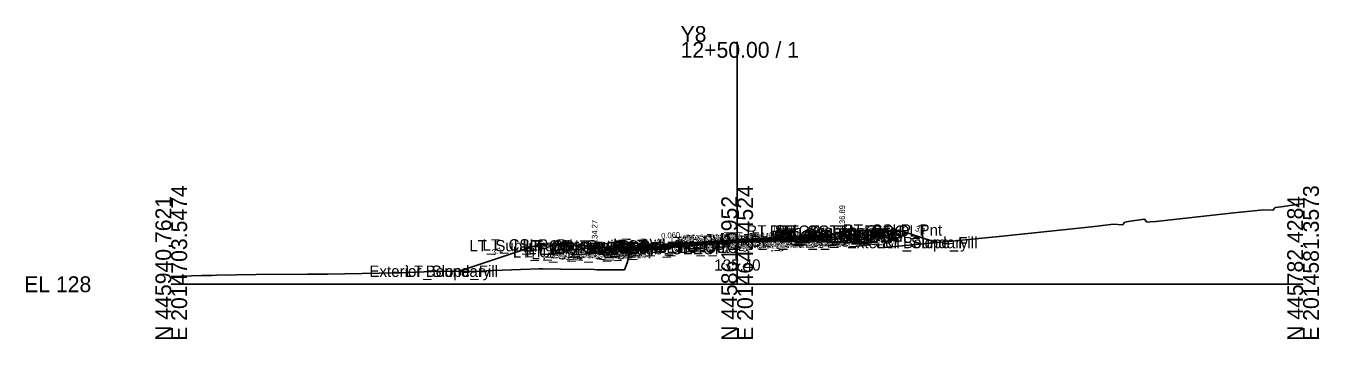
# Model space of a CAD drawing. Extents: x -26 to 1403, y -10 to 8043.
# Drawn here: x -25.7 to 202.8, y 4990.3 to 5045.6 of the extents above; entities that cross this region are included whole.
import ezdxf

# ---------------------------------------------------------------- set-up
doc = ezdxf.new("R2010")
doc.units = 0
for name, color, linetype in [('Default', 7, 'Continuous'), ('Exist CMT Pavement', 7, 'Continuous'), ('Exist Cross Section Cell', 7, 'Continuous'), ('Exist XS Center Line Elevation Label', 7, 'Continuous'), ('Exist XS Ground Line', 7, 'Continuous'), ('Prop CMT Conc Surface', 7, 'Continuous'), ('Prop CMT Concrete Structures', 7, 'Continuous'), ('Prop CMT Pvmt Course 1', 7, 'Continuous'), ('Prop CMT Pvmt Course 1 CG', 7, 'Continuous'), ('Prop CMT Pvmt Course 1 Wedge', 7, 'Continuous'), ('Prop CMT Pvmt Course 2', 7, 'Continuous'), ('Prop CMT Pvmt Course 2 Wedge', 7, 'Continuous'), ('Prop CMT Pvmt Course 3', 7, 'Continuous'), ('Prop CMT Pvmt Course 3 Wedge', 7, 'Continuous'), ('Prop CMT Pvmt Surface', 7, 'Continuous'), ('Prop CMT Pvmt Wedge Surface 1', 7, 'Continuous'), ('Prop CMT Pvmt Wedge Surface 2', 7, 'Continuous'), ('Prop CMT Pvmt Wedge Surface 3', 7, 'Continuous'), ('Prop CMT Slope Grass', 7, 'Continuous'), ('Prop CMT Subgrade Earthwork', 7, 'Continuous'), ('Prop XS Earthwork Shape', 7, 'Continuous'), ('Prop XS Hydro Elevations', 7, 'Continuous'), ('Prop XS SE Text', 7, 'Continuous'), ('Prop XS Side Slope Text', 7, 'Continuous'), ('Prop XS Wedging', 7, 'Continuous'), ('Scratch_Level_0', 7, 'Continuous')]:
    doc.layers.add(name, color=color, linetype=linetype)

msp = doc.modelspace()

# ---------------------------------------------------------------- linework, layer by layer
at = {"layer": 'Exist CMT Pavement'}
msp.add_lwpolyline([(88.23, 5006.52), (90.89, 5006.74), (99.12, 5007.37), (100, 5007.4), (105.99, 5007.58), (107.65, 5007.65), (107.65, 5007.65)], dxfattribs=at)
at = {"layer": 'Exist Cross Section Cell'}
for p, q in [((100, 5000), (100, 5042.8)), ((0, 5000), (100, 5000)), ((100, 5000), (200, 5000))]:
    msp.add_line(p, q, dxfattribs=at)
at = {"layer": 'Exist XS Ground Line'}
msp.add_lwpolyline([(0, 5001.36), (5.4, 5001.53), (7.09, 5001.55), (8.04, 5001.58), (15.03, 5001.75), (24.09, 5001.78), (27.66, 5001.81), (39.75, 5002), (40.46, 5002.01), (47.5, 5002.33), (52.93, 5002.28), (54.63, 5002.33), (56.83, 5002.4), (65.03, 5002.72), (65.65, 5002.7), (68.86, 5002.65), (74.71, 5002.59), (75.24, 5002.56), (78.78, 5002.55), (80.09, 5002.56), (80.59, 5003.81), (81.22, 5006.05), (86.99, 5006.42), (88.23, 5006.52), (90.89, 5006.74), (99.12, 5007.37), (100, 5007.4), (105.99, 5007.58), (107.65, 5007.65), (109.17, 5007.71), (110.08, 5007.71), (111.02, 5007.97), (112.19, 5007.9), (114.59, 5007.88), (116.98, 5007.6), (117.9, 5007.54), (120.35, 5007.32), (122.79, 5007.18), (124.31, 5007.03), (124.61, 5006.96), (125.03, 5006.46), (126.61, 5006.56), (138.59, 5007.68), (140.8, 5007.9), (146.27, 5008.41), (162.62, 5010.13), (166.53, 5010.6), (168.11, 5010.49), (168.53, 5010.99), (169.53, 5011.15), (172, 5011.47), (172.42, 5010.97), (172.96, 5011.01), (174, 5011.07), (187.78, 5012.59), (193.09, 5013.17), (194.67, 5013.07), (195.09, 5013.57), (196.15, 5013.69), (200, 5014.27)], dxfattribs=at)
at = {"layer": 'Prop CMT Conc Surface'}
for points in [[(116.56, 5008.85), (118.56, 5008.89)], [(118.56, 5008.89), (118.56, 5009.39), (119.06, 5009.39)], [(74.82, 5006.27), (74.82, 5006.77), (74.32, 5006.77)], [(76.82, 5006.47), (74.82, 5006.27)]]:
    msp.add_lwpolyline(points, dxfattribs=at)
at = {"layer": 'Prop CMT Concrete Structures'}
for points in [[(116.56, 5008.85), (118.56, 5008.89), (118.56, 5009.39), (119.06, 5009.39)], [(119.06, 5009.39), (119.06, 5008.42), (116.56, 5008.27)], [(116.56, 5008.27), (116.56, 5008.85)], [(76.82, 5006.47), (74.82, 5006.27), (74.82, 5006.77), (74.32, 5006.77)], [(74.32, 5006.77), (74.32, 5005.73), (76.82, 5005.88)], [(76.82, 5005.88), (76.82, 5006.47)]]:
    msp.add_lwpolyline(points, dxfattribs=at)
at = {"layer": 'Prop CMT Pvmt Course 1'}
for points in [[(100, 5007.86), (76.82, 5006.47)], [(88.23, 5007.03), (100, 5007.73)], [(100, 5007.86), (116.56, 5008.85)], [(107.65, 5008.19), (100, 5007.73)], [(100, 5007.61), (100, 5007.86)], [(100, 5007.61), (100, 5007.86)], [(100, 5007.73), (100, 5007.61), (100, 5007.61)], [(100, 5007.73), (100, 5007.61), (100, 5007.61)], [(116.56, 5008.6), (107.65, 5008.07)], [(107.65, 5008.07), (107.65, 5008.19)], [(116.56, 5008.85), (116.56, 5008.6)], [(76.82, 5006.22), (88.23, 5006.9)], [(76.82, 5006.47), (76.82, 5006.22)], [(88.23, 5006.9), (88.23, 5007.03)]]:
    msp.add_lwpolyline(points, dxfattribs=at)
at = {"layer": 'Prop CMT Pvmt Course 1 CG'}
for points in [[(116.56, 5008.27), (119.56, 5008.45), (119.83, 5008.17)], [(116.56, 5007.97), (116.56, 5008.27)], [(119.83, 5008.17), (116.56, 5007.97)], [(76.82, 5005.88), (73.82, 5005.7), (73.51, 5005.39)], [(73.51, 5005.39), (76.82, 5005.59)], [(76.82, 5005.59), (76.82, 5005.88)]]:
    msp.add_lwpolyline(points, dxfattribs=at)
at = {"layer": 'Prop CMT Pvmt Course 1 Wedge'}
for points in [[(100, 5007.73), (88.23, 5007.03)], [(100, 5007.73), (107.65, 5008.19)]]:
    msp.add_lwpolyline(points, dxfattribs=at)
at = {"layer": 'Prop CMT Pvmt Course 2'}
for points in [[(107.65, 5008.07), (116.56, 5008.6)], [(116.56, 5008.35), (107.65, 5007.82)], [(107.65, 5007.82), (107.65, 5008.07)], [(116.56, 5008.6), (116.56, 5008.35)], [(88.23, 5006.9), (76.82, 5006.22)], [(76.82, 5005.97), (88.23, 5006.65)], [(76.82, 5006.22), (76.82, 5005.97)], [(88.23, 5006.65), (88.23, 5006.9)]]:
    msp.add_lwpolyline(points, dxfattribs=at)
at = {"layer": 'Prop CMT Pvmt Course 2 Wedge'}
for points in [[(100, 5007.61), (88.23, 5006.9)], [(100, 5007.61), (107.65, 5008.07)]]:
    msp.add_lwpolyline(points, dxfattribs=at)
at = {"layer": 'Prop CMT Pvmt Course 3'}
for points in [[(107.65, 5007.82), (116.56, 5008.35)], [(116.56, 5007.97), (107.65, 5007.44)], [(107.65, 5007.44), (107.65, 5007.82)], [(116.56, 5008.35), (116.56, 5007.97)], [(88.23, 5006.65), (76.82, 5005.97)], [(76.82, 5005.59), (88.23, 5006.28)], [(76.82, 5005.97), (76.82, 5005.59)], [(88.23, 5006.28), (88.23, 5006.65)]]:
    msp.add_lwpolyline(points, dxfattribs=at)
at = {"layer": 'Prop CMT Pvmt Course 3 Wedge'}
for points in [[(100, 5007.36), (88.23, 5006.65)], [(100, 5007.36), (107.65, 5007.82)]]:
    msp.add_lwpolyline(points, dxfattribs=at)
at = {"layer": 'Prop CMT Pvmt Surface'}
for points in [[(100, 5007.86), (76.82, 5006.47)], [(100, 5007.86), (116.56, 5008.85)]]:
    msp.add_lwpolyline(points, dxfattribs=at)
at = {"layer": 'Prop CMT Pvmt Wedge Surface 1'}
for points in [[(100, 5007.73), (88.23, 5007.03)], [(100, 5007.73), (107.65, 5008.19)], [(107.65, 5008.07), (116.56, 5008.6)], [(107.65, 5008.19), (107.65, 5008.07)], [(116.56, 5008.6), (116.56, 5008.85)], [(88.23, 5006.9), (76.82, 5006.22)], [(76.82, 5006.22), (76.82, 5006.47)], [(88.23, 5007.03), (88.23, 5006.9)]]:
    msp.add_lwpolyline(points, dxfattribs=at)
at = {"layer": 'Prop CMT Pvmt Wedge Surface 2'}
for points in [[(100, 5007.61), (76.82, 5006.22)], [(100, 5007.61), (116.56, 5008.6)], [(116.56, 5008.6), (116.56, 5008.85)], [(76.82, 5006.22), (76.82, 5006.47)]]:
    msp.add_lwpolyline(points, dxfattribs=at)
at = {"layer": 'Prop CMT Pvmt Wedge Surface 3'}
for points in [[(100, 5007.36), (76.82, 5005.97)], [(100, 5007.36), (116.56, 5008.35)], [(116.56, 5008.35), (116.56, 5008.85)], [(76.82, 5005.97), (76.82, 5006.47)]]:
    msp.add_lwpolyline(points, dxfattribs=at)
at = {"layer": 'Prop CMT Slope Grass'}
for points in [[(119.06, 5009.39), (128.56, 5009.58), (135.21, 5007.36)], [(74.32, 5006.77), (64.82, 5006.96), (50.86, 5002.3)]]:
    msp.add_lwpolyline(points, dxfattribs=at)
at = {"layer": 'Prop CMT Subgrade Earthwork'}
for points in [[(107.65, 5007.44), (116.56, 5007.97)], [(107.65, 5007.44), (107.65, 5007.65)], [(116.56, 5007.97), (119.83, 5008.17), (121.09, 5009.43)], [(76.82, 5005.59), (73.51, 5005.39), (72.09, 5006.81)], [(88.23, 5006.28), (76.82, 5005.59)], [(88.23, 5006.28), (88.23, 5006.52)]]:
    msp.add_lwpolyline(points, dxfattribs=at)
at = {"layer": 'Prop XS Earthwork Shape'}
for points in [[(114.71, 5007.86), (116.98, 5007.6), (117.9, 5007.54), (120.35, 5007.32), (122.79, 5007.18), (124.31, 5007.03), (124.61, 5006.96), (125.03, 5006.46), (126.61, 5006.56), (135.21, 5007.36), (128.56, 5009.58), (121.09, 5009.43), (119.83, 5008.17), (116.56, 5007.97)], [(114.71, 5007.86), (116.98, 5007.6), (117.9, 5007.54), (120.35, 5007.32), (122.79, 5007.18), (124.31, 5007.03), (124.61, 5006.96), (125.03, 5006.46), (126.61, 5006.56), (135.21, 5007.36), (128.56, 5009.58), (121.09, 5009.43), (119.83, 5008.17), (116.56, 5007.97)], [(110.08, 5007.71), (111.02, 5007.97), (112.19, 5007.9), (114.59, 5007.88), (114.71, 5007.86), (107.65, 5007.44), (107.65, 5007.65), (109.17, 5007.71)], [(109.17, 5007.71), (110.08, 5007.71), (111.02, 5007.97), (112.19, 5007.9), (114.59, 5007.88), (114.71, 5007.86), (107.65, 5007.44), (107.65, 5007.65)], [(72.09, 5006.81), (64.82, 5006.96), (50.86, 5002.3), (52.93, 5002.28), (54.63, 5002.33), (56.83, 5002.4), (65.03, 5002.72), (65.65, 5002.7), (68.86, 5002.65), (74.71, 5002.59), (75.24, 5002.56), (78.78, 5002.55), (80.09, 5002.56), (80.59, 5003.81), (81.16, 5005.85), (76.82, 5005.59), (73.51, 5005.39)], [(81.16, 5005.85), (76.82, 5005.59), (73.51, 5005.39), (72.09, 5006.81), (64.82, 5006.96), (50.86, 5002.3), (52.93, 5002.28), (54.63, 5002.33), (56.83, 5002.4), (65.03, 5002.72), (65.65, 5002.7), (68.86, 5002.65), (74.71, 5002.59), (75.24, 5002.56), (78.78, 5002.55), (80.09, 5002.56), (80.59, 5003.81)], [(81.16, 5005.85), (81.22, 5006.05), (86.99, 5006.42), (88.23, 5006.52), (88.23, 5006.28)], [(81.16, 5005.85), (81.22, 5006.05), (86.99, 5006.42), (88.23, 5006.52), (88.23, 5006.28)]]:
    msp.add_lwpolyline(points, close=True, dxfattribs=at)
at = {"layer": 'Prop XS Wedging'}
for p, q in [((100, 5007.73), (88.23, 5007.03)), ((88.23, 5006.9), (97.42, 5007.45)), ((97.42, 5007.45), (88.23, 5006.9)), ((95.19, 5007.07), (97.61, 5007.25)), ((97.42, 5007.45), (100, 5007.61)), ((100, 5007.61), (97.42, 5007.45)), ((97.61, 5007.25), (97.42, 5007.45)), ((97.42, 5007.45), (97.61, 5007.25)), ((97.61, 5007.25), (97.42, 5007.45)), ((97.61, 5007.25), (99.12, 5007.37)), ((107.65, 5008.19), (100, 5007.73)), ((100, 5007.61), (100, 5007.73)), ((100, 5007.73), (100, 5007.61)), ((100.23, 5007.62), (100, 5007.61)), ((100.01, 5007.4), (100.23, 5007.62)), ((100.01, 5007.4), (100.23, 5007.62)), ((100.23, 5007.62), (100.01, 5007.4)), ((100.01, 5007.4), (101.36, 5007.44)), ((107.65, 5008.07), (100.23, 5007.62)), ((101.36, 5007.44), (107.65, 5007.82)), ((107.65, 5007.82), (101.36, 5007.44)), ((101.36, 5007.44), (105.99, 5007.58)), ((105.99, 5007.58), (107.65, 5007.65)), ((107.65, 5008.07), (107.65, 5008.19)), ((107.65, 5007.82), (107.65, 5008.07)), ((107.65, 5007.65), (107.65, 5007.82)), ((88.23, 5006.65), (95.19, 5007.07)), ((95.19, 5007.07), (88.23, 5006.65)), ((88.23, 5007.03), (88.23, 5006.9)), ((88.23, 5006.9), (88.23, 5006.65)), ((88.23, 5006.52), (90.89, 5006.74)), ((88.23, 5006.65), (88.23, 5006.52)), ((90.89, 5006.74), (95.19, 5007.07))]:
    msp.add_line(p, q, dxfattribs=at)
for points in [[(99.12, 5007.37), (100, 5007.4), (100.01, 5007.4)], [(100, 5007.61), (100.23, 5007.62), (107.65, 5008.07)], [(100.01, 5007.4), (100.01, 5007.4)], [(100.01, 5007.4), (100.01, 5007.4)]]:
    msp.add_lwpolyline(points, dxfattribs=at)

# ---------------------------------------------------------------- texts
at = {"layer": 'Default'}
msp.add_text('-', height=0.0001, dxfattribs=at).set_placement((0, 5000))
at = {"layer": 'Exist Cross Section Cell'}
for s, p in [('Y8', (90, 5042.8)), ('12+50.00 / 1', (90, 5040)), ('EL 128', (-26, 4998.6))]:
    msp.add_text(s, height=2.8, dxfattribs=at).set_placement(p)
for s, p in [('E 2014703.5474', (2.8, 4990)), ('E 2014642.4524', (102.8, 4990)), ('E 2014581.3573', (202.8, 4990)), ('N 445940.7621', (0, 4990)), ('N 445861.5952', (100, 4990)), ('N 445782.4284', (200, 4990))]:
    msp.add_text(s, height=2.8, rotation=90, dxfattribs=at).set_placement(p)
at = {"layer": 'Exist XS Center Line Elevation Label'}
msp.add_text('135.40', height=2, dxfattribs=at).set_placement((95.95, 5002.4))
at = {"layer": 'Prop XS Hydro Elevations'}
for s, p in [('136.89', (119.06, 5009.89)), ('134.27', (75.32, 5007.27))]:
    msp.add_text(s, height=1, rotation=90, dxfattribs=at).set_placement(p)
at = {"layer": 'Prop XS SE Text'}
for p in [(106.47, 5009.25), (86.6, 5008.05)]:
    msp.add_text('0.060', height=1, rotation=3.4336, dxfattribs=at).set_placement(p)
at = {"layer": 'Prop XS Side Slope Text'}
for rotation, p in [(341.5668, (131.37, 5009.43)), (18.4332, (56.85, 5005.09))]:
    msp.add_text('3:1', height=1, rotation=rotation, dxfattribs=at).set_placement(p)
at = {"layer": 'Scratch_Level_0'}
for s, p in [('RT_Sub_Trench_Out_DLT', (101.61, 5008.43)), ('RT_CG_Top_Face', (105.77, 5008.39)), ('RT_CG1_Shelf_Out', (106.06, 5007.45)), ('RT_PV2_OEOT', (106.68, 5007.6)), ('RT_CG_Top_Gut', (106.75, 5007.89)), ('RT_PV1_OEOT', (107.25, 5007.85)), ('RT_CG_Top_BOC', (107.29, 5008.39)), ('RT_CG_Bot_BOC', (107.33, 5007.42)), ('RT_CSLP_Pnt', (118.68, 5008.58)), ('LT_Sub_Trench_Out_DLT', (52.66, 5005.81)), ('LT_CSLP_Pnt', (54.99, 5005.96)), ('LT_CG_Top_Face', (62.08, 5005.77)), ('LT_CG_Top_BOC', (62.6, 5005.77)), ('LT_CG_Top_Gut', (63.05, 5005.27)), ('LT_PV2_OEOT', (66.99, 5005.22)), ('LT_PV1_OEOT', (67.56, 5005.47)), ('LT_PV_Sub_Tie_Out', (73.19, 5005.52)), ('LT_PV_OEEOP_EG', (75.77, 5005.52)), ('LT_Sub_OEEOP', (77.44, 5005.28)), ('LT_PV2_OEEOP', (77.54, 5005.9)), ('LT_PV3_OEEOP', (77.54, 5005.65)), ('LT_PV1_OEEOP', (78.1, 5006.03)), ('RT_PV_IEEOP_EG', (88.14, 5006.4)), ('LT_PV_IEEOP_EG', (88.19, 5006.4)), ('RT_PV2_IEEOP', (89.91, 5006.61)), ('RT_PV3_IEEOP', (89.91, 5006.36)), ('LT_PV2_IEEOP', (89.95, 5006.61)), ('LT_PV3_IEEOP', (89.95, 5006.36)), ('RT_PV1_IEEOP', (90.47, 5006.73)), ('LT_PV1_IEEOP', (90.52, 5006.73)), ('RT_PV_Sub_Tie_Out', (92.53, 5006.65)), ('PV2_PGL', (93.91, 5006.61)), ('PV1_PGL', (94.47, 5006.86)), ('RT_PV_OEEOP_EG', (95.15, 5006.65)), ('RT_Sub_OEEOP', (96.81, 5006.44)), ('RT_PV2_OEEOP', (96.91, 5007.07)), ('RT_PV3_OEEOP', (96.91, 5006.82)), ('RT_PV1_OEEOP', (97.48, 5007.19)), ('RT_CG_Bot_IE', (106.42, 5007.27)), ('RT_Sub_OEOT', (106.59, 5006.97)), ('RT_PV3_OEOT', (106.68, 5007.35)), ('RT_Sub_OEOP', (109.9, 5007.17)), ('Exterior Boundary', (119.35, 5006.36)), ('RT_Slope_Fill', (125.68, 5006.36)), ('LT_CG1_Shelf_Out', (60.37, 5004.7)), ('LT_CG_Bot_BOC', (62.63, 5004.73)), ('LT_Sub_OEOP', (63.62, 5004.39)), ('LT_CG_Bot_IE', (66.73, 5004.88)), ('LT_Sub_OEOT', (66.9, 5004.59)), ('LT_PV3_OEOT', (66.99, 5004.97)), ('Exterior Boundary', (35, 5001.3)), ('LT_Slope_Fill', (41.38, 5001.3))]:
    msp.add_text(s, height=2, dxfattribs=at).set_placement(p)

doc.saveas('drawing.dxf')
